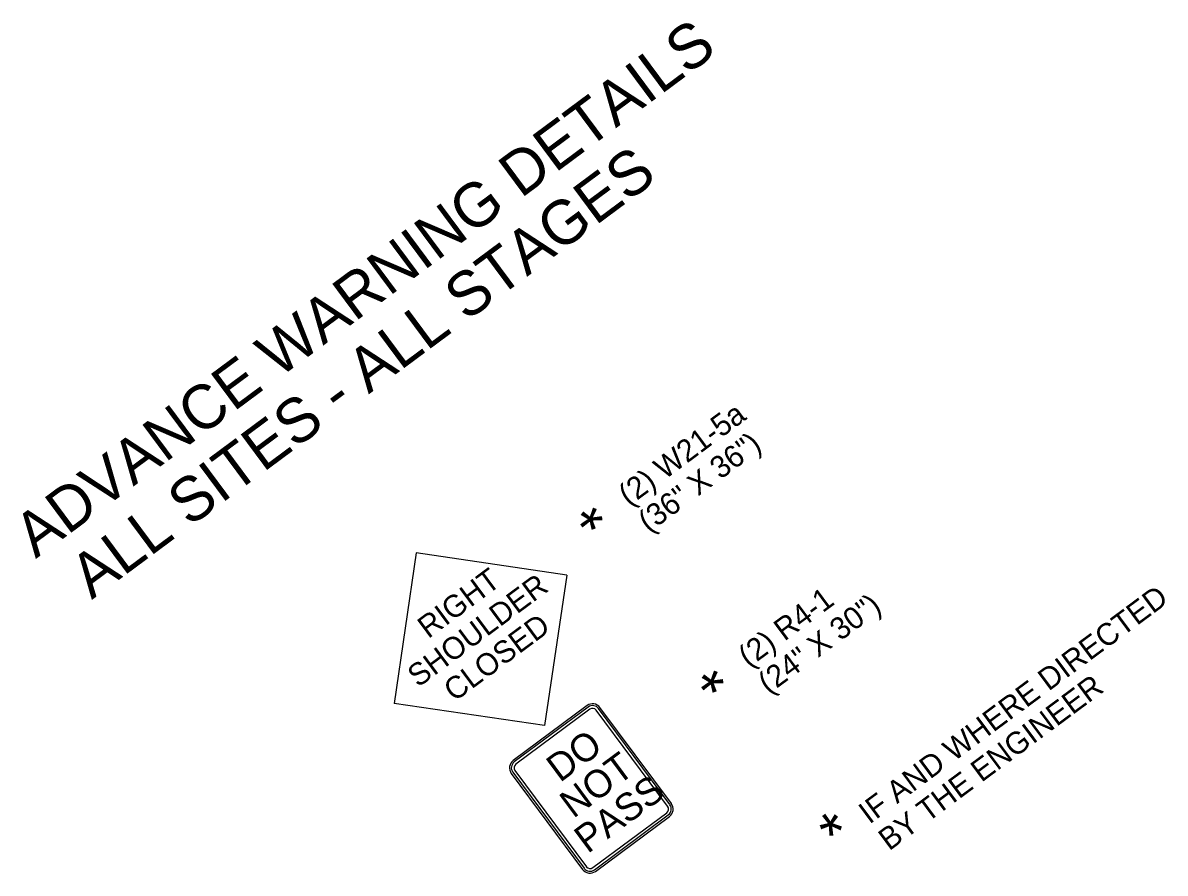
# Model space of a CAD drawing. Extents: x -238 to 1487, y -1123 to 446.
# Drawn here: x 659.2 to 969.4, y -767.2 to -536.3 of the extents above; entities that cross this region are included whole.
import ezdxf

# ---------------------------------------------------------------- set-up
doc = ezdxf.new("R2010")
doc.units = 0
doc.layers.add('P_TC_Signs_Permanent', color=7, linetype='Continuous')
doc.layers.add('R_Border Prem', color=7, linetype='Continuous')

msp = doc.modelspace()

# ---------------------------------------------------------------- linework, layer by layer
at = {"layer": 'P_TC_Signs_Permanent'}
for p, q in [((812.42, -721.68), (792.34, -736.58)), ((812.71, -722.08), (792.64, -736.98)), ((813.16, -722.68), (793.09, -737.58)), ((834.89, -748.58), (815.51, -722.49)), ((835.29, -748.29), (815.91, -722.19)), ((834.29, -749.03), (814.91, -722.94)), ((791.83, -740.08), (811.2, -766.17)), ((792.23, -739.78), (811.6, -765.87)), ((792.83, -739.33), (812.21, -765.43)), ((813.96, -765.68), (834.03, -750.78)), ((814.4, -766.29), (834.47, -751.38)), ((814.7, -766.69), (834.77, -751.78))]:
    msp.add_line(p, q, dxfattribs=at)
for centre, radius, start, end in [((813.91, -723.68), 2.5, 36.5953, 126.5953), ((813.91, -723.68), 2, 36.5953, 126.5953), ((813.91, -723.68), 1.25, 36.5953, 126.5953), ((793.84, -738.59), 2.5, 126.5953, 216.5953), ((793.84, -738.59), 2, 126.5953, 216.5953), ((793.84, -738.59), 1.25, 126.5953, 216.5953), ((833.28, -749.78), 1.25, 306.5953, 36.5953), ((833.28, -749.78), 2, 306.5953, 36.5953), ((833.28, -749.78), 2.5, 306.5953, 36.5953), ((813.21, -764.68), 2, 216.5953, 306.5953), ((813.21, -764.68), 1.25, 216.5953, 306.5953), ((813.21, -764.68), 2.5, 216.5953, 306.5953)]:
    msp.add_arc(centre, radius, start, end, dxfattribs=at)
at = {"layer": 'R_Border Prem'}
for p, q in [((766.04, -680.18), (759.99, -721.09)), ((806.95, -686.23), (766.04, -680.18)), ((806.95, -686.23), (800.89, -727.12)), ((800.89, -727.12), (759.99, -721.09))]:
    msp.add_line(p, q, dxfattribs=at)

# ---------------------------------------------------------------- texts
at = {"layer": 'P_TC_Signs_Permanent'}
for s, rotation, p in [('DO', 36.5953, (805.04, -742.73)), ('NOT', 36.555, (808.66, -752.48)), ('PASS', 36.5953, (812.58, -762.03))]:
    msp.add_text(s, height=7.5, rotation=rotation, dxfattribs=at).set_placement(p)
at = {"layer": 'R_Border Prem'}
for s, height, rotation, p in [('ADVANCE WARNING DETAILS', 12, 36.5953, (662.71, -681.9)), ('ALL SITES - ALL STAGES', 12, 36.5953, (677.92, -693.03)), ('(2) W21-5a', 6, 36.5953, (823.79, -667.67)), ('(36" X 36")', 6, 36.5953, (829.15, -674.89)), ('*', 12, 126.5953, (822.35, -668.26)), ('RIGHT ', 6, 36.5958, (769.29, -703.65)), ('SHOULDER', 6, 36.5958, (766.54, -716.9)), ('(2) R4-1', 6, 36.5953, (856.34, -711.51)), ('IF AND WHERE DIRECTED ', 6, 36.5953, (889.07, -754.04)), ('(24" X 30")', 6, 36.5953, (861.7, -718.73)), ('CLOSED', 6, 36.5958, (776.38, -720.8)), ('*', 12, 126.5953, (855.2, -712.5)), ('BY THE ENGINEER', 6, 36.5953, (894.44, -761.27)), ('*', 12, 36.5953, (881.28, -762.85))]:
    msp.add_text(s, height=height, rotation=rotation, dxfattribs=at).set_placement(p)

doc.saveas('drawing.dxf')
